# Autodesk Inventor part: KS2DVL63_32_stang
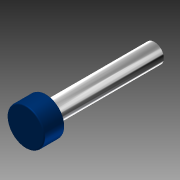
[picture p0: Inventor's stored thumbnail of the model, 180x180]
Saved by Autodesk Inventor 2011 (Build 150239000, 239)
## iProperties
Created: 2010-10
Document SubType Name: Modeling
Designer: TB
Mass: 161.233 g
Surface Area: 236.814 cm^2
Volume: 161.233 cm^3
Density: 1 g/cm^3
Author: TB
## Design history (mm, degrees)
sketch "Sketch2"
  geometry: L1 (-35, -3)-(-35, 3) reference; L2 (-35, -9)-(-35, 9) reference; L3 (-35, 16)-(-258, 16); L4 (-258, 16)-(-258, 0); L5 (-258, 0)-(-35, 0); L6 (-35, 0)-(-35, 16); L7 (-258, 16)-(-223, 16); L8 (-223, 16)-(-223, 31.5); L9 (-223, 31.5)-(-258, 31.5); L10 (-258, 31.5)-(-258, 16); 1 further point
  constraints: 16 end point, 4 parallel, 2 horizontal, 2 perpendicular, 1 midpoint
  dimensions: "Dia" = 32 diameter of L3 L5; "d3" = 223 distance of L3.start L3.end (computed from Slaglengde, Forlengelse_rør); "StempelDia" = 63 diameter of L9 L5; "StempelLengde" = 35 distance of L8.end L9.end
revolve "Revolution1" sketch "Sketch2" stored, may be unused: angle "d6" = 90 deg
fillet "Fillet1" dims "d7" = 2
sketch "Sketch3"
  geometry: L1 (-258, -29.5)-(-258, 29.5) reference; L2 (-258, 0)-(-258.01, 0); L3 (-258, 0)-(-258, 0.01); A1 r 0.01 centre (-258, 0) between (-258, 0.01) and (-258.01, 0); 1 further point
  constraints: 4 end point, 2 point on circle, 1 centre point, 1 midpoint, 1 perpendicular, 1 point on line
  dimensions: "d8" = 0.01 distance of L2.start L2.end; "d9" = 0.01 distance of L2.start L3.end (= d8); "d10" = 0.01 radius of A1 (= d8)
revolve "Revolution2" sketch "Sketch3" stored, may be unused: angle "d11" = 90 deg
body "Solid1"
node "Projected Loop2"
other parameters: "Forlengelse_rør" = 0
